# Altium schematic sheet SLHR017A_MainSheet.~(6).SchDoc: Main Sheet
size 431 x 279 mm; Date: Not shown in title block; ApprovedBy: Not shown in title block; CheckedBy: Not shown in title block; Author: Not shown in title block; CompanyName: Not shown in title block; DrawnBy: Kirby Kruckmeyer; Engineer: Not shown in title block; Organization: Not shown in title block; Address1: Not shown in title block; Address2: Not shown in title block; Address3: Not shown in title block; Address4: Not shown in title block; DocumentNumber: 1; Revision: Use project parameter SCH_Rev; SheetNumber: 1; SheetTotal: 2; PageSetup: Record=PageOptions¦CenterHorizontal=True¦CenterVertical=True¦PrintScale=1.00¦XCorrection=1.00¦YCorrection=1.00¦PrintKind=0¦BorderSize=5000000¦LeftOffset=0¦BottomOffset=0¦Orientation=2¦PaperLength=1000¦PaperWidth=1000¦Scale=100¦PaperSource=15¦PrintQuality=600¦MediaType=1¦DitherType=10¦PaperKind=Letter¦PrintScaleMode=1
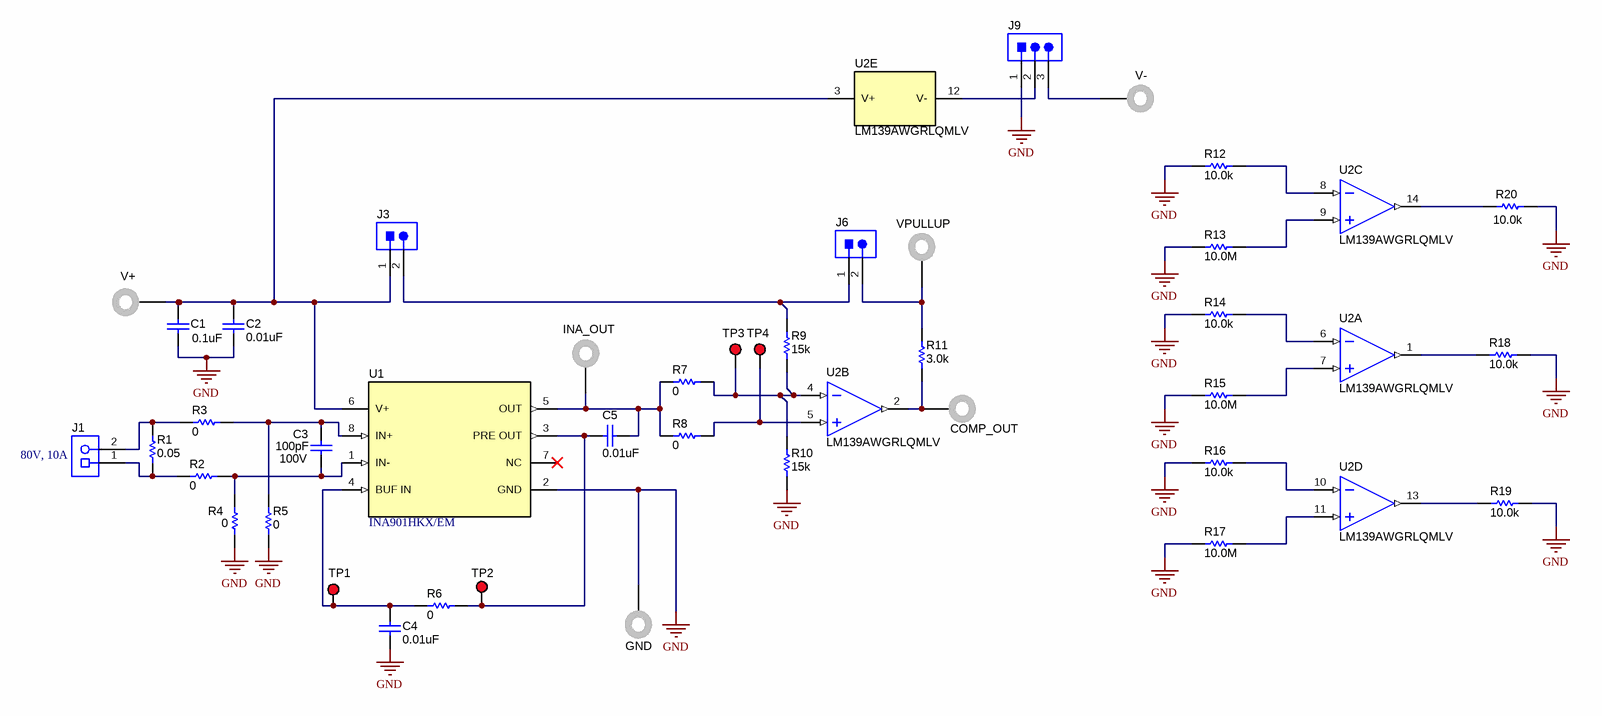
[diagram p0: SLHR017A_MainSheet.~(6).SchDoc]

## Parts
C1  ValueDisplayed: 0.1uF  [0805_HV]  (hidden comment: C0805C104K1RACTU)
C2  ValueDisplayed: 0.01uF  [0805_HV]  (hidden comment: C0805C103F1GACTU)
C3  Cap_F: 100pF  VDC_V: 100V  [0805_HV]  (hidden comment: C0805C101J1RACTU)
C4  ValueDisplayed: 0.01uF  [0805_HV]  (hidden comment: C0805C103F1GACTU)
C5  ValueDisplayed: 0.01uF  [0805_HV]  (hidden comment: C0805C103F1GACTU)
J1  039544-3002  [Molex_039544-3002]  (value not drawn)
J2  V+  [Keystone_575-4]
J3  PBC02SAAN  [Sullins_PBC02SAAN]  (value not drawn)
J4  INA_OUT  [Keystone_575-4]
J5  GND  [Keystone_575-4]
J6  PBC02SAAN  [Sullins_PBC02SAAN]  (value not drawn)
J7  VPULLUP  [Keystone_575-4]
J8  COMP_OUT  [Keystone_575-4]
J9  TSW-103-07-G-S  [TSW-103-07-G-S]  (value not drawn)
J10  V-  [Keystone_575-4]
R1  ValueDisplayed: 0.05  [4320]  (hidden comment: KRL11050-C-R050-F-T1)
R2  ValueDisplayed: 0  [0805_HV]  (hidden comment: ERJ-6GEY0R00V)
R3  ValueDisplayed: 0  [0805_HV]  (hidden comment: ERJ-6GEY0R00V)
R4  ValueDisplayed: 0  [0805_HV]  (hidden comment: ERJ-6GEY0R00V)
R5  ValueDisplayed: 0  [0805_HV]  (hidden comment: ERJ-6GEY0R00V)
R6  ValueDisplayed: 0  [0805_HV]  (hidden comment: ERJ-6GEY0R00V)
R7  ValueDisplayed: 0  [0805_HV]  (hidden comment: ERJ-6GEY0R00V)
R8  ValueDisplayed: 0  [0805_HV]  (hidden comment: ERJ-6GEY0R00V)
R9  ValueDisplayed: 15k  [0805_HV]  (hidden comment: ERJ-6GEYJ153V)
R10  ValueDisplayed: 15k  [0805_HV]  (hidden comment: ERJ-6GEYJ153V)
R11  ValueDisplayed: 3.0k  [0805_HV]  (hidden comment: ERJ-6GEYJ302V)
R12  ValueDisplayed: 10.0k  [0805_HV]  (hidden comment: RNCP0805FTD10K0)
R13  ValueDisplayed: 10.0M  [0805_HV]  (hidden comment: CRCW080510M0FKEA)
R14  ValueDisplayed: 10.0k  [0805_HV]  (hidden comment: RNCP0805FTD10K0)
R15  ValueDisplayed: 10.0M  [0805_HV]  (hidden comment: CRCW080510M0FKEA)
R16  ValueDisplayed: 10.0k  [0805_HV]  (hidden comment: RNCP0805FTD10K0)
R17  ValueDisplayed: 10.0M  [0805_HV]  (hidden comment: CRCW080510M0FKEA)
R18  ValueDisplayed: 10.0k  [0805_HV]  (hidden comment: RNCP0805FTD10K0)
R19  ValueDisplayed: 10.0k  [0805_HV]  (hidden comment: RNCP0805FTD10K0)
R20  ValueDisplayed: 10.0k  [0805_HV]  (hidden comment: RNCP0805FTD10K0)
TP1  5010  [Keystone5010]  (value not drawn)
TP2  5010  [Keystone5010]  (value not drawn)
TP3  5010  [Keystone5010]  (value not drawn)
TP4  5010  [Keystone5010]  (value not drawn)
U1  INA901HKX/EM  [HKX0008A_Custom_B]
U2  LM139AWGRLQMLV  [NAC0014A_N]  (parts A,B,C,D,E of 5)

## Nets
GND: C1.2 C2.2 C4.2 J5.1 J9.1 R4.1 R5.1 R10.1 R12.1 R13.1 R14.1 R15.1 R16.1 R17.1 R18.2 R19.2 R20.2 U1.2(GND)
NetC1_1: C1.1 C2.1 J2.1 J3.1 U1.6(V+) U2.3(V+)
NetC3_1: C3.1 R3.2 R5.2 U1.8(IN+)
NetC3_2: C3.2 R2.2 R4.2 U1.1(IN-)
NetC4_1: C4.1 R6.1 TP1.1 U1.4(BUF_IN)
NetC5_1: C5.1 R6.2 TP2.1 U1.3(PRE_OUT)
NetC5_2: C5.2 J4.1 R7.1 R8.1 U1.5(OUT)
NetJ1_1: J1.1 R1.1 R2.1
NetJ1_2: J1.2 R1.2 R3.1
NetJ3_2: J3.2 J6.1 R9.2
NetJ6_2: J6.2 J7.1 R11.2
NetJ8_1: J8.1 R11.1 U2.2(OUT1)
NetJ9_2: J9.2 U2.12(V-)
NetJ9_3: J9.3 J10.1
NetR7_2: R7.2 R9.1 R10.2 TP3.1 U2.4(-IN1)
NetR8_2: R8.2 TP4.1 U2.5(+IN1)
NetR12_2: R12.2 U2.8(-IN3)
NetR13_2: R13.2 U2.9(+IN3)
NetR14_2: R14.2 U2.6(-IN2)
NetR15_2: R15.2 U2.7(+IN2)
NetR16_2: R16.2 U2.10(-IN4)
NetR17_2: R17.2 U2.11(+IN4)
NetR18_1: R18.1 U2.1(OUT2)
NetR19_1: R19.1 U2.13(OUT4)
NetR20_1: R20.1 U2.14(OUT3)

Not connected (* = marked no-connect by the designer): U1 7(NC)*

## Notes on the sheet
- (near J1) 80V, 10A

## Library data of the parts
C1 = CMP-0007722-2: CAP, CERM, 0.1 uF, 100 V, +/- 10%, X7R, 0805; Manufacturer: Kemet; TaMin_C: -55°C; ESR_ohm: 0.064; Polarized: N; SizeAreaWB_mm2: 6.75; Value1: 0.064 ohm; U/M: EA; Value: 0.1uF; TaMax_C: 125°C; SizeZ_mm: 1.45; SizeX_mm: 2; SizeY_mm: 1.25; Cap_Case: 0805; Value2: 100V; SizeArea_mm2: 2.5; Cap_F: 100nF; IRMS_A: 1.64A; AEC Category: Q200
C2 C4 C5 = CMP-0007716-2: CAP, CERM, 0.01 uF, 100 V, +/- 1%, C0G/NP0, 0805; Manufacturer: Kemet; TaMin_C: -55°C; Polarized: N; SizeAreaWB_mm2: 6.75; Value1: Unknown; U/M: EA; Value: 0.01uF; TaMax_C: 125°C; SizeZ_mm: 1.45; SizeX_mm: 2; SizeY_mm: 1.25; Cap_Case: 0805; Value2: 100V; SizeArea_mm2: 2.5; Cap_F: 10nF; AEC Category: Q200
C3 = CMP-0007706-2: CAP, CERM, 100 pF, 100 V, +/- 5%, X7R, 0805; Manufacturer: Kemet; TaMin_C: -55°C; Polarized: N; SizeAreaWB_mm2: 6.75; Value1: Unknown; U/M: EA; Value: 100pF; TaMax_C: 125°C; SizeZ_mm: 1.45; SizeX_mm: 2; SizeY_mm: 1.25; Cap_Case: 0805; SizeArea_mm2: 2.5; AEC Category: Q200
J1 = CMP-0055345-1: Terminal Block, 5.08mm, 2x1, TH; Manufacturer: Molex; CNHeader: FALSE; Current_A: 15A; Gender: Female; Voltage_V: 300V; Row_Count: 1; Pitch_mm: 5.08; ContactFinish: Tin; CT: TRUE; Cert_UL: Y
J2 J4 J5 J7 J8 J10 = CMP-0055165-2: Standard Banana Jack, Uninsulated, 5.5mm; Manufacturer: Keystone; PartNumber: 575-4; CT: TRUE; Green_REACh: Passed; CNHeader: FALSE; Green_Lifecycle: Active
J3 J6 = CMP-0054566-1: Header, 100mil, 2x1, Gold, TH; Manufacturer: Sullins Connector Solutions; CNHeader: TRUE; Current_A: 3A; Green_Lifecycle: Active; Shrouded: N; Gender: Male; Green_REACh: Passed; Voltage_V: 1.8kV; Row_Count: 1; Pitch_mm: 2.54; CT: FALSE; Cert_UL: Y
J9 = CMP-0075407-2: Header, 100mil, 3x1, Gold, TH; Manufacturer: Samtec; Pitch_mm: 2.54; Cert_VDE: N; Gender: Male; Cert_CSA: Y; Voltage_V: 550V; Green_REACh: Passed; Current_A: 6.3A; Green_Lifecycle: Active; Row_Count: 1
R1 = CMP-0015099-2: RES, 0.05, 1%, 6 W, 4320_WIDE; Manufacturer: Susumu Co Ltd; Power_W: 6W; TempCo: 50 ppm/C; Value_Code: R050; U/M: EA; Value: 0.05; EIA_Code: E96; AEC Category: Q200
R2-R8 = CMP-0020616-3: RES, 0, 5%, 0.125 W, AEC-Q200 Grade 0, 0805; Manufacturer: Panasonic; Power_W: 125mW; TempCo: 600 ppm/C; Value_Code: 0000; Value: 0; EIA_Code: E24; SizeX_mm: 2; SizeY_mm: 1.25; SizeZ_mm: 1.45; Value2: 0.125W; SizeArea_mm2: 2.5; AEC Qualified: Y; VDC_V: 150V; AEC Category: Q200; SizeAreaWB_mm2: 6.75
R9 R10 = CMP-0020646-3: RES, 15 k, 5%, 0.125 W, AEC-Q200 Grade 0, 0805; Manufacturer: Panasonic; Power_W: 125mW; TempCo: 200 ppm/C; Value_Code: 15k0; Value: 15k; EIA_Code: E24; SizeX_mm: 2; SizeY_mm: 1.25; SizeZ_mm: 1.45; Value2: 0.125W; SizeArea_mm2: 2.5; AEC Qualified: Y; VDC_V: 150V; AEC Category: Q200; AEC Grade: 0; SizeAreaWB_mm2: 6.75
R11 = CMP-0020698-3: RES, 3.0 k, 5%, 0.125 W, AEC-Q200 Grade 0, 0805; Manufacturer: Panasonic; Power_W: 125mW; TempCo: 200 ppm/C; Value_Code: 3k00; Value: 3.0k; EIA_Code: E24; Res_ohm: 3k; SizeX_mm: 2; SizeY_mm: 1.25; SizeZ_mm: 1.45; Value2: 0.125W; SizeArea_mm2: 2.5; AEC Qualified: Y; VDC_V: 150V; AEC Category: Q200; AEC Grade: 0; SizeAreaWB_mm2: 6.75
R12 R14 R16 R18-R20 = CMP-0084247-1: RES, 10.0 k, 1%, 0.25 W, AEC-Q200 Grade 0, 0805; Manufacturer: Stackpole Electronics Inc; Power_W: 250mW; Green_Lifecycle: Active; TempCo: 100 ppm/C; SizeAreaWB_mm2: 6.75; Value_Code: 10k0; Green_REACh: Passed; Value: 10.0k; EIA_Code: E96; Res_ohm: 10k; SizeX_mm: 2; SizeY_mm: 1.25; SizeZ_mm: 1.45; Value2: 0.25W; SizeArea_mm2: 2.5; AEC Qualified: Y; AEC Grade: 0; AEC Category: Q200
R13 R15 R17 = CMP-0020846-3: RES, 10.0 M, 1%, 0.125 W, AEC-Q200 Grade 0, 0805; Manufacturer: Vishay-Dale; Power_W: 125mW; TempCo: 100 ppm/C; Value_Code: 10M0; Value: 10.0Meg; EIA_Code: E96; Res_ohm: 10M; SizeX_mm: 2; SizeY_mm: 1.25; SizeZ_mm: 1.45; Value2: 0.125W; SizeArea_mm2: 2.5; AEC Qualified: Y; VDC_V: 150V; AEC Category: Q200; AEC Grade: 0
TP1-TP4 = CMP-0055147-1: Test Point, Multipurpose, Red, TH; Manufacturer: Keystone; CNHeader: FALSE; Green_Lifecycle: Active; Green_REACh: Passed; ContactFinish: Silver; CT: TRUE
U1 = CMP-0081563-2: Voltage Output, Unidirectional Measurement Current-Shunt Monitor, HKX0008A (CFP-8); Manufacturer: Texas Instruments; SizeZ_mm: 2.8; Rating: Space; AEC Category: Q200; CompType: IC; AEC Qualified: N
U2 = CMP-0068426-2: Low Power Low Offset Voltage Quad Comparator, NAC0014A (CFP-14); Manufacturer: Texas Instruments; AEC Qualified: N; SizeX_mm: 10.41; SizeArea_mm2: 103.16; SizeZ_mm: 2.03; Rating: Space; CompType: Amplifiers; AEC Category: Q200; SizeAreaWB_mm2: 147.8; SizeY_mm: 9.91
